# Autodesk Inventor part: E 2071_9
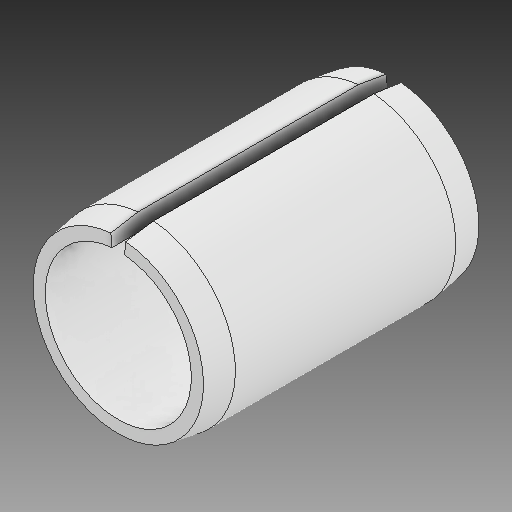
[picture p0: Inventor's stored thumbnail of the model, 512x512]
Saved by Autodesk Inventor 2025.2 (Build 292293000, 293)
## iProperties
Created: 2025-04
Part Number: E 2071_9
Material: Všeobecné
Document SubType Name: Modeling
Designer: Patrik
Density: 1 g/cm^3
Appearance: Výchozí
Author: Patrik
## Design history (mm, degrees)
feature "Base1"
node "Těleso1"
